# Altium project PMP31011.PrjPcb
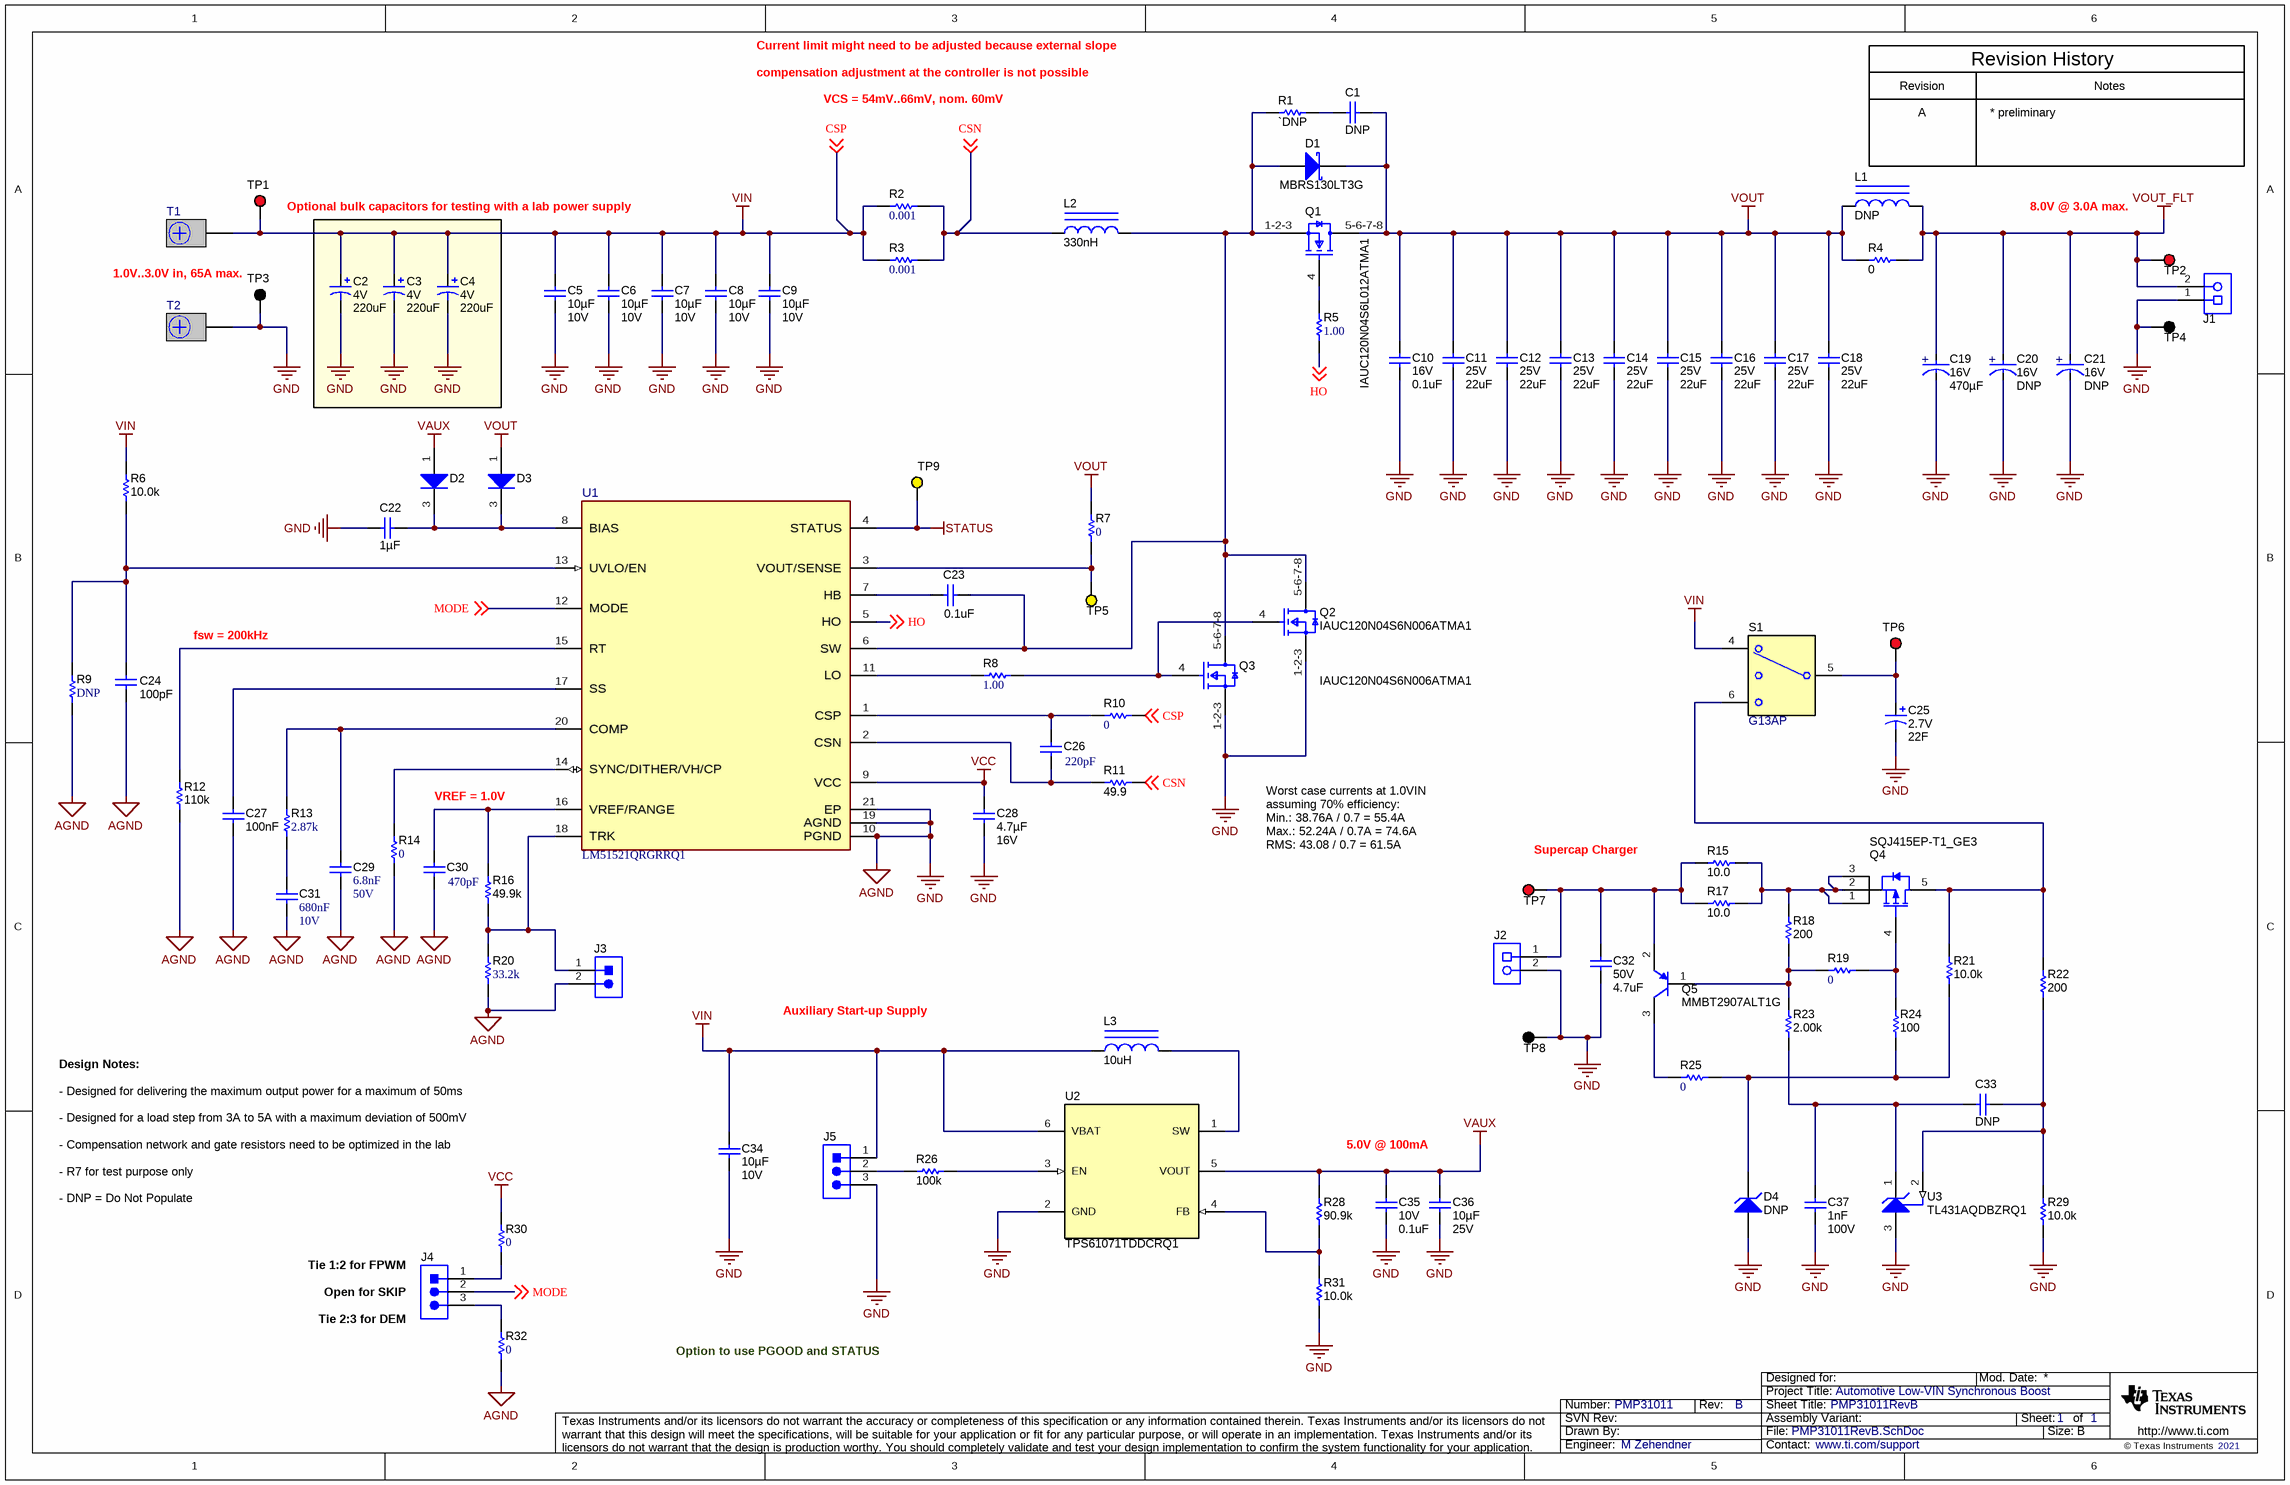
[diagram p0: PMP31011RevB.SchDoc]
TechSupport: www.ti.com/support; SCH_Rev: B; PRJ_Title: Automotive Low-VIN Synchronous Boost; PRJ_Number: PMP31011; PRJ_Engineer: M Zehendner; CopyrightYear: 2021
1 sheet, 100 parts. Net scope: global (net labels, ports and power ports of the same name join across sheets).
Board file: PMP31011_PCB.PcbDoc

## Sheet PMP31011RevB.SchDoc: PMP31011RevB
size 431 x 279 mm; DocumentNumber: 1; Revision: A; SheetNumber: 1; SheetTotal: 1; PageSetup: Record=PageOptions¦CenterHorizontal=True¦CenterVertical=True¦PrintScale=0.62¦XCorrection=1.00¦YCorrection=1.00¦PrintKind=0¦BorderSize=5000000¦LeftOffset=0¦BottomOffset=0¦Orientation=2¦PaperLength=1000¦PaperWidth=1000¦Scale=100¦PaperSource=15¦PrintQuality=600¦MediaType=1¦DitherType=10¦PaperKind=Letter (8.5 x 11")¦PrintScaleMode=1

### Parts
C1  Cap_F: DNP  [0805_HV]  (hidden comment: GRM21BR72A153MA01L)
C2  VDC_V: 4V  ValueDisplayed: 220uF  [7343-20]  (hidden comment: EEFSX0G221ER)
C3  VDC_V: 4V  ValueDisplayed: 220uF  [7343-20]  (hidden comment: EEFSX0G221ER)
C4  VDC_V: 4V  ValueDisplayed: 220uF  [7343-20]  (hidden comment: EEFSX0G221ER)
C5  Cap_F: 10µF  VDC_V: 10V  [0603]  (hidden comment: GRM188Z71A106MA73D)
C6  Cap_F: 10µF  VDC_V: 10V  [0603]  (hidden comment: GRM188Z71A106MA73D)
C7  Cap_F: 10µF  VDC_V: 10V  [0603]  (hidden comment: GRM188Z71A106MA73D)
C8  Cap_F: 10µF  VDC_V: 10V  [0603]  (hidden comment: GRM188Z71A106MA73D)
C9  Cap_F: 10µF  VDC_V: 10V  [0603]  (hidden comment: GRM188Z71A106MA73D)
C10  VDC_V: 16V  ValueDisplayed: 0.1uF  [0402]  (hidden comment: GRM155R71C104JA88D)
C11  VDC_V: 25V  ValueDisplayed: 22uF  [1210_270]  (hidden comment: GRM32ER71E226KE15L)
C12  VDC_V: 25V  ValueDisplayed: 22uF  [1210_270]  (hidden comment: GRM32ER71E226KE15L)
C13  VDC_V: 25V  ValueDisplayed: 22uF  [1210_270]  (hidden comment: GRM32ER71E226KE15L)
C14  VDC_V: 25V  ValueDisplayed: 22uF  [1210_270]  (hidden comment: GRM32ER71E226KE15L)
C15  VDC_V: 25V  ValueDisplayed: 22uF  [1210_270]  (hidden comment: GRM32ER71E226KE15L)
C16  VDC_V: 25V  ValueDisplayed: 22uF  [1210_270]  (hidden comment: GRM32ER71E226KE15L)
C17  VDC_V: 25V  ValueDisplayed: 22uF  [1210_270]  (hidden comment: GRM32ER71E226KE15L)
C18  VDC_V: 25V  ValueDisplayed: 22uF  [1210_270]  (hidden comment: GRM32ER71E226KE15L)
C19  VDC_V: 16V  Cap_F: 470µF  [FP-HHXB160ARA471MJA0G_RADIAL-MFG]  (hidden comment: HHXB160ARA471MJA0G)
C20  VDC_V: 16V  Cap_F: DNP  [FP-HHXB160ARA471MJA0G_RADIAL-MFG]  (hidden comment: HHXB160ARA471MJA0G)
C21  VDC_V: 16V  Cap_F: DNP  [FP-HHXB160ARA471MJA0G_RADIAL-MFG]  (hidden comment: HHXB160ARA471MJA0G)
C22  Cap_F: 1µF  [0603]  (hidden comment: GRM188R71E105KA12D)
C23  ValueDisplayed: 0.1uF  [0402]  (hidden comment: GRM155R71H104ME14D)
C24  ValueDisplayed: 100pF  [0402]  (hidden comment: GRM1555C1H101JA01D)
C25  VDC_V: 2.7V  ValueDisplayed: 22F  [JUM_1600x3150]  (hidden comment: JUMT1226MHD)
C26  ValueDisplayed: 220pF  [0402]  (hidden comment: GRM155R71H221KA01D)
C27  Cap_F: 100nF  [0603]  (hidden comment: GRM188R71C104KA01D)
C28  Cap_F: 4.7µF  VDC_V: 16V  [0603]  (hidden comment: GRM188Z71C475KE21D)
C29  Cap_F: 6.8nF  VDC_V: 50V  [0603]  (hidden comment: GRM188R71H682KA01D)
C30  ValueDisplayed: 470pF  [0402]  (hidden comment: GRM1555C1H471JA01D)
C31  Cap_F: 680nF  VDC_V: 10V  [0603]  (hidden comment: GRM188R71A684KA61D)
C32  VDC_V: 50V  ValueDisplayed: 4.7uF  [1210_270]  (hidden comment: GRM32ER71H475KA88L)
C33  Cap_F: DNP  [0603]  (hidden comment: GRM188R72A102KA01D)
C34  Cap_F: 10µF  VDC_V: 10V  [0603]  (hidden comment: GRM188Z71A106MA73D)
C35  VDC_V: 10V  ValueDisplayed: 0.1uF  [0402]  (hidden comment: GRM155R71A104KA01D)
C36  Cap_F: 10µF  VDC_V: 25V  [0805_HV]  (hidden comment: GRM21BZ71E106KE15L)
C37  Cap_F: 1nF  VDC_V: 100V  [0603]  (hidden comment: GRM188R72A102KA01D)
D1  MBRS130LT3G  [SMB]
D2  BAS16LT1G  [SOT-23]  (value not drawn)
D3  BAS16LT1G  [SOT-23]  (value not drawn)
D4  DNP  [SOD-523]
J1  691 101 710 002  [Wurth_691101710002]  (value not drawn)
J2  691 101 710 002  [Wurth_691101710002]  (value not drawn)
J3  61300211121  [WURTH_61300211121]  (value not drawn)
J4  61300311121  [WURTH_61300311121]  (value not drawn)
J5  61300311121  [WURTH_61300311121]  (value not drawn)
L1  ValueDisplayed: DNP  [XEL4014]  (hidden comment: XEL4014-221MEB)
L2  Ind_H: 330nH  [FP-ETQP8MR33JFA_SMT_INDUCTOR_12MM6_13MM2-MFG]  (hidden comment: ETQP8MR33JFA)
L3  ValueDisplayed: 10uH  [LPS4018]  (hidden comment: LPS4018-103MRB)
Q1  IAUC120N04S6L012ATMA1  [FP-IAUC120N04S6N009ATMA1_TDSON8-MFG]
Q2  IAUC120N04S6N006ATMA1  [FP-IAUC120N04S6N009ATMA1_TDSON8-MFG]
Q3  IAUC120N04S6N006ATMA1  [FP-IAUC120N04S6N009ATMA1_TDSON8-MFG]
Q4  SQJ415EP-T1_GE3  [PowerPAK_SO-8L]
Q5  MMBT2907ALT1G  [SOT-23]
R1  ValueDisplayed: `DNP  [1206]  (hidden comment: CSR1206FTR820)
R2  ValueDisplayed: 0.001  [2512]  (hidden comment: ERJ-M1WTF1M0U)
R3  ValueDisplayed: 0.001  [2512]  (hidden comment: ERJ-M1WTF1M0U)
R4  ValueDisplayed: 0  [2512_WIDE_VISHAY]  (hidden comment: RCL12250000Z0EG)
R5  ValueDisplayed: 1.00  [0603]  (hidden comment: CRCW06031R00FKEA)
R6  ValueDisplayed: 10.0k  [0603]  (hidden comment: CRCW060310K0FKEA)
R7  ValueDisplayed: 0  [0603]  (hidden comment: CRCW06030000Z0EA)
R8  ValueDisplayed: 1.00  [0603]  (hidden comment: CRCW06031R00FKEA)
R9  ValueDisplayed: DNP  [0603]  (hidden comment: CRCW06030000Z0EA)
R10  ValueDisplayed: 0  [0402]  (hidden comment: CRCW04020000Z0ED)
R11  ValueDisplayed: 49.9  [0402]  (hidden comment: CRCW040249R9FKED)
R12  ValueDisplayed: 110k  [0603]  (hidden comment: CRCW0603110KFKEA)
R13  ValueDisplayed: 2.87k  [0603]  (hidden comment: CRCW06032K87FKEA)
R14  ValueDisplayed: 0  [0402]  (hidden comment: CRCW04020000Z0ED)
R15  ValueDisplayed: 10.0  [1206]  (hidden comment: CRCW120610R0FKEA)
R16  ValueDisplayed: 49.9k  [0603]  (hidden comment: CRCW060349K9FKEA)
R17  ValueDisplayed: 10.0  [1206]  (hidden comment: CRCW120610R0FKEA)
R18  ValueDisplayed: 200  [0603]  (hidden comment: CRCW0603200RFKEA)
R19  ValueDisplayed: 0  [0603]  (hidden comment: CRCW06030000Z0EA)
R20  ValueDisplayed: 33.2k  [0603]  (hidden comment: CRCW060333K2FKEA)
R21  ValueDisplayed: 10.0k  [0603]  (hidden comment: CRCW060310K0FKEA)
R22  ValueDisplayed: 200  [0603]  (hidden comment: CRCW0603200RFKEA)
R23  ValueDisplayed: 2.00k  [0603]  (hidden comment: CRCW06032K00FKEA)
R24  ValueDisplayed: 100  [0603]  (hidden comment: CRCW0603100RFKEA)
R25  ValueDisplayed: 0  [0603]  (hidden comment: CRCW06030000Z0EA)
R26  ValueDisplayed: 100k  [0603]  (hidden comment: CRCW0603100KJNEA)
R28  ValueDisplayed: 90.9k  [0402]  (hidden comment: CRCW040290K9FKED)
R29  ValueDisplayed: 10.0k  [0603]  (hidden comment: CRCW060310K0FKEA)
R30  ValueDisplayed: 0  [0603]  (hidden comment: CRCW06030000Z0EA)
R31  ValueDisplayed: 10.0k  [0402]  (hidden comment: CRCW040210K0FKED)
R32  ValueDisplayed: 0  [0603]  (hidden comment: CRCW06030000Z0EA)
S1  G13AP  [SW_G1xAP]
T1  CB35-36-CY  [CB35-36-CY]  (value not drawn)
T2  CB35-36-CY  [CB35-36-CY]  (value not drawn)
TP1  5010  [Keystone5010]  (value not drawn)
TP2  5010  [Keystone5010]  (value not drawn)
TP3  5011  [Keystone5011]  (value not drawn)
TP4  5011  [Keystone5011]  (value not drawn)
TP5  5014  [Keystone5014]  (value not drawn)
TP6  5010  [Keystone5010]  (value not drawn)
TP7  5010  [Keystone5010]  (value not drawn)
TP8  5011  [Keystone5011]  (value not drawn)
TP9  5014  [Keystone5014]  (value not drawn)
U1  LM51521QRGRRQ1  [RGR0020C-MFG]
U2  TPS61071TDDCRQ1  [DDC0006A_N]
U3  TL431AQDBZRQ1  [DBZ0003A_N]

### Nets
AGND: C2.2(-) C3.2(-) C4.2(-) C5.2 C6.2 C7.2 C8.2 C9.2 C10.2 C11.2 C12.2 C13.2 C14.2 C15.2 C16.2 C17.2 C18.2 C19.1(CATHODE) C20.1(CATHODE) C21.1(CATHODE) C22.2 C24.2 C25.2(-) C27.2 C28.2 C29.2 C30.2 C31.2 C32.2 C34.2 C35.2 C36.2 C37.2 D4.2(A) J1.1 J2.2 J3.2 J5.3 Q2.1-2-3(S) Q3.1-2-3(S) R9.1 R12.1 R14.1 R20.1 R29.1 R31.1 R32.1 T2.1 TP3.1 TP4.1 TP8.1 U1.10(PGND) U1.19(AGND) U1.21(EP) U2.2(GND) U3.3(ANODE)  [also labelled GND]
STATUS: TP9.1 U1.4(STATUS)
VAUX: C35.1 C36.1 D2.1(A) R28.2 U2.5(VOUT)
VCC: C28.1 R30.2 U1.9(VCC)
VIN: C2.1(+) C3.1(+) C4.1(+) C5.1 C6.1 C7.1 C8.1 C9.1 C34.1 J5.1 L3.1 R2.2 R3.2 R6.2 R10.2 S1.4 T1.1 TP1.1 U2.6(VBAT) ; off-sheet CSP  [also labelled CSP]
VOUT: C1.1 C10.1 C11.1 C12.1 C13.1 C14.1 C15.1 C16.1 C17.1 C18.1 D1.1(K) D3.1(A) L1.1 Q1.5-6-7-8(D) R4.1 R7.2
VOUT_FLT: C19.2(ANODE) C20.2(ANODE) C21.2(ANODE) J1.2 L1.2 R4.2 TP2.1
CSN: L2.1 R2.1 R3.1 R11.2 ; off-sheet CSN
HO: R5.1 U1.5(HO) ; off-sheet HO
MODE: J4.2 U1.12(MODE) ; off-sheet MODE
NetC1_2: C1.2 R1.2
NetC22_1: C22.1 D2.3(K) D3.3(K) U1.8(BIAS)
NetC23_1: C23.1 U1.7(HB)
NetC23_2: C23.2 D1.2(A) L2.2 Q1.1-2-3(S) Q2.5-6-7-8(D) Q3.5-6-7-8(D) R1.1 U1.6(SW)
NetC24_1: C24.1 R6.1 R9.2 U1.13(UVLO/EN)
NetC25_1: C25.1(+) S1.5(COM) TP6.1
NetC26_1: C26.1 R10.1 U1.1(CSP)
NetC26_2: C26.2 R11.1 U1.2(CSN)
NetC27_1: C27.1 U1.17(SS)
NetC29_1: C29.1 R13.2 U1.20(COMP)
NetC30_1: C30.1 R16.2 U1.16(VREF/RANGE)
NetC31_1: C31.1 R13.1
NetC32_1: C32.1 J2.1 Q5.2(E) R15.1 R17.1 TP7.1
NetC33_1: C33.1 C37.1 R23.1 U3.1(CATHODE)
NetC33_2: C33.2 R22.1 R29.2 U3.2(REF)
NetD4_1: D4.1(K) R21.1 R24.1 R25.2
NetJ3_1: J3.1 R16.1 R20.2 U1.18(TRK)
NetJ4_1: J4.1 R30.1
NetJ4_3: J4.3 R32.2
NetJ5_2: J5.2 R26.2
NetL3_2: L3.2 U2.1(SW)
NetQ1_4: Q1.4(G) R5.2
NetQ2_4: Q2.4(G) Q3.4(G) R8.1
NetQ4_1: Q4.1(S) Q4.2(S) Q4.3(S) R15.2 R17.2 R18.2
NetQ4_4: Q4.4(G) R19.2 R24.2
NetQ4_5: Q4.5(D) R21.2 R22.2 S1.6
NetQ5_1: Q5.1(B) R18.1 R19.1 R23.2
NetQ5_3: Q5.3(C) R25.1
NetR7_1: R7.1 TP5.1 U1.3(VOUT/SENSE)
NetR8_2: R8.2 U1.11(LO)
NetR12_2: R12.2 U1.15(RT)
NetR14_2: R14.2 U1.14(SYNC/DITHER/VH/CP)
NetR26_1: R26.1 U2.3(EN)
NetR28_1: R28.1 R31.2 U2.4(FB)

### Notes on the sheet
- Current limit might need to be adjusted because external slope
- compensation adjustment at the controller is not possible
- VCS = 54mV..66mV, nom. 60mV
- Revision
- Revision History
- Notes
- A
- * preliminary
- (near TP1) Optional bulk capacitors for testing with a lab power supply
- 8.0V @ 3.0A max.
- 1.0V..3.0V in, 65A max.
- fsw = 200kHz
- VREF = 1.0V
- Worst case currents at 1.0VIN assuming 70% efficiency:
  Min.: 38.76A / 0.7 = 55.4A
  Max.: 52.24A / 0.7A = 74.6A
  RMS: 43.08 / 0.7 = 61.5A
- (near TP7) Supercap Charger
- Auxiliary Start-up Supply
- Design Notes:
- - Designed for delivering the maximum output power for a maximum of 50ms
- - Designed for a load step from 3A to 5A with a maximum deviation of 500mV
- - R7 for test purpose only
- - Compensation network and gate resistors need to be optimized in the lab
- 5.0V @ 100mA
- - DNP = Do Not Populate
- (near J4) Tie 1:2 for FPWM
- (near J4) Open for SKIP
- (near J4) Tie 2:3 for DEM
- Option to use PGOOD and STATUS

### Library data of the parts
C1 = CMP-0008366-2: CAP, CERM, 0.015 uF, 100 V, +/- 20%, X7R, 0805; Manufacturer: MuRata; TaMin_C: -55°C; Polarized: N; SizeAreaWB_mm2: 6.75; Value1: Unknown; U/M: EA; TaMax_C: 125°C; SizeZ_mm: 1.45; SizeX_mm: 2; SizeY_mm: 1.25; Cap_Case: 0805; Value2: 100V; SizeArea_mm2: 2.5; AEC Category: Q200
C2-C4 = CMP-0012259-4: CAP, Aluminum Polymer, 220 uF, 4 V, +/- 20%, 9 ohm, 7343-20, SMD; Manufacturer: Panasonic; TaMin_C: -40°C; ESR_ohm: 9; Polarized: Y; Value1: 9 ohm; Value: 220uF; TaMax_C: 105°C; CompType: Capacitor; AEC Qualified: N; Cap_F: 220µF; IRMS_A: 3A; AEC Category: Q200; SizeAreaWB_mm2: 58.59; SizeArea_mm2: 31.39; SizeX_mm: 7.3; SizeY_mm: 4.3; SizeZ_mm: 2.0
C5-C9 C34 = CMP-0007497-5: CAP, CERM, 10 uF, 10 V, +/- 20%, X7R, 0603; Manufacturer: MuRata; TaMin_C: -55°C; Polarized: N; SizeAreaWB_mm2: 4.68; Value1: Unknown; U/M: EA; Value: 10uF; TaMax_C: 125°C; SizeZ_mm: 1; SizeX_mm: 1.6; SizeY_mm: 0.8; SizeArea_mm2: 1.28; AEC Category: Q200
C10 = CMP-0006640-2: CAP, CERM, 0.1 uF, 16 V, +/- 5%, X7R, 0402; Manufacturer: MuRata; TaMin_C: -55°C; Polarized: N; SizeAreaWB_mm2: 3; Value1: Unknown; U/M: EA; Value: 0.1uF; TaMax_C: 125°C; SizeZ_mm: 0.6; SizeX_mm: 1; SizeY_mm: 0.5; Cap_F: 100nF; AEC Category: Q200
C11-C18 = CMP-0009224-2: CAP, CERM, 22 uF, 25 V, +/- 10%, X7R, 1210; Manufacturer: MuRata; TaMin_C: -55°C; Polarized: N; SizeAreaWB_mm2: 14.7; Value1: Unknown; U/M: EA; Value: 22uF; TaMax_C: 125°C; SizeZ_mm: 2.7; SizeX_mm: 3.2; SizeY_mm: 2.5; Cap_Case: 1210; SizeArea_mm2: 8; Cap_F: 22µF; AEC Category: Q200
C19-C21 = CMP-0086437-1: Cap Aluminum Polymer 470uF 16VDC 20% (10 X 10mm) SMD 0.018 Ohm 2600mA 5000h 105C Automotive T/R; Manufacturer: United Chemi-Con; AEC Qualified: Yes; SizeZ_mm: 10.3mm; IRMS_A: 2.6A; Symbol Name: SYM-HHXB160ARA471MJA0G; AEC Grade: Grade 2
C22 = CMP-0007405-4: CAP, CERM, 1 uF, 25 V, +/- 10%, X7R, 0603; Manufacturer: MuRata; TaMin_C: -55°C; Polarized: N; SizeAreaWB_mm2: 4.68; Value1: Unknown; U/M: EA; Value: 1uF; TaMax_C: 125°C; SizeZ_mm: 1; SizeX_mm: 1.6; SizeY_mm: 0.8; Value2: 25V; SizeArea_mm2: 1.28; AEC Category: Q200
C23 = CMP-0006675-2: CAP, CERM, 0.1 uF, 50 V, +/- 20%, X7R, 0402; Manufacturer: MuRata; TaMin_C: -55°C; Polarized: N; SizeAreaWB_mm2: 3; Value1: Unknown; U/M: EA; Value: 0.1uF; TaMax_C: 125°C; SizeZ_mm: 0.6; SizeX_mm: 1; SizeY_mm: 0.5; Value2: 50V; Cap_F: 100nF; AEC Category: Q200
C24 = CMP-0006410-2: CAP, CERM, 100 pF, 50 V, +/- 5%, C0G/NP0, 0402; Manufacturer: MuRata; TaMin_C: -55°C; Polarized: N; SizeAreaWB_mm2: 3; Value1: Unknown; U/M: EA; Value: 100pF; TaMax_C: 125°C; SizeZ_mm: 0.6; SizeX_mm: 1; SizeY_mm: 0.5; Value2: 50V; AEC Category: Q200
C25 = CMP-0084050-1: CAP, Electric Double Layer, 22000000 µF, 2.7 V,+/- 20%, 0.07 ohm, TH; Manufacturer: Nichicon; TaMin_C: -25°C; ESR_ohm: 0.07; Polarized: Y; SizeAreaWB_mm2: 324; Value: 22000000uF; TaMax_C: 70°C; SizeZ_mm: 33.5; SizeX_mm: 16; Cap_Case: 16x31.5mm; SizeArea_mm2: 256; CompType: Capacitor; AEC Qualified: N; AEC Category: Q200
C26 = CMP-0006682-2: CAP, CERM, 220 pF, 50 V, +/- 10%, X7R, 0402; Manufacturer: MuRata; TaMin_C: -55°C; Polarized: N; SizeAreaWB_mm2: 3; Value1: Unknown; U/M: EA; Value: 220pF; TaMax_C: 125°C; SizeZ_mm: 0.6; SizeX_mm: 1; SizeY_mm: 0.5; Value2: 50V; AEC Category: Q200
C27 = CMP-0007378-5: CAP, CERM, 0.1 uF, 16 V, +/- 10%, X7R, 0603; Manufacturer: MuRata; TaMin_C: -55°C; Polarized: N; SizeAreaWB_mm2: 4.68; Value1: Unknown; U/M: EA; Value: 0.1uF; TaMax_C: 125°C; SizeZ_mm: 1; SizeX_mm: 1.6; SizeY_mm: 0.8; Value2: 16V; SizeArea_mm2: 1.28; AEC Category: Q200
C28 = CMP-0064936-4: CAP, CERM, 4.7 uF, 16 V,+/- 10%, X7R, 0603; Manufacturer: MuRata; TaMin_C: -55°C; Polarized: N; SizeAreaWB_mm2: 4.68; Value1: Unknown; U/M: EA; Value: 4.7uF; TaMax_C: 125°C; SizeZ_mm: 1; SizeX_mm: 1.6; SizeY_mm: 0.8; SizeArea_mm2: 1.28; AEC Category: Q200
C29 = CMP-0007462-4: CAP, CERM, 6800 pF, 50 V, +/- 10%, X7R, 0603; Manufacturer: MuRata; TaMin_C: -55°C; Polarized: N; SizeAreaWB_mm2: 4.68; Value1: Unknown; U/M: EA; Value: 6800pF; TaMax_C: 125°C; SizeZ_mm: 1; SizeX_mm: 1.6; SizeY_mm: 0.8; SizeArea_mm2: 1.28; AEC Category: Q200
C30 = CMP-0006470-2: CAP, CERM, 470 pF, 50 V, +/- 5%, C0G/NP0, 0402; Manufacturer: MuRata; TaMin_C: -55°C; Polarized: N; SizeAreaWB_mm2: 3; Value1: Unknown; U/M: EA; Value: 470pF; TaMax_C: 125°C; SizeZ_mm: 0.6; SizeX_mm: 1; SizeY_mm: 0.5; Value2: 50V; AEC Category: Q200
C31 = CMP-0007375-4: CAP, CERM, 0.68 uF, 10 V, +/- 10%, X7R, 0603; Manufacturer: MuRata; TaMin_C: -55°C; Polarized: N; SizeAreaWB_mm2: 4.68; Value1: Unknown; U/M: EA; Value: 0.68uF; TaMax_C: 125°C; SizeZ_mm: 1; SizeX_mm: 1.6; SizeY_mm: 0.8; SizeArea_mm2: 1.28; AEC Category: Q200
C32 = CMP-0009228-2: CAP, CERM, 4.7 uF, 50 V, +/- 10%, X7R, 1210; Manufacturer: MuRata; TaMin_C: -55°C; ESR_ohm: 2m; Polarized: N; SizeAreaWB_mm2: 14.7; Value1: 0.002 ohm; U/M: EA; Value: 4.7uF; TaMax_C: 125°C; SizeZ_mm: 2.7; SizeX_mm: 3.2; SizeY_mm: 2.5; Cap_Case: 1210; SizeArea_mm2: 8; Cap_F: 4.7µF; AEC Category: Q200
C33 = CMP-0007467-4: CAP, CERM, 1000 pF, 100 V, +/- 10%, X7R, 0603; Manufacturer: MuRata; TaMin_C: -55°C; Polarized: N; SizeAreaWB_mm2: 4.68; Value1: Unknown; U/M: EA; Value: 1000pF; TaMax_C: 125°C; SizeZ_mm: 1; SizeX_mm: 1.6; SizeY_mm: 0.8; Value2: 100V; SizeArea_mm2: 1.28; AEC Category: Q200
C35 = CMP-0006629-2: CAP, CERM, 0.1 uF, 10 V, +/- 10%, X7R, 0402; Manufacturer: MuRata; TaMin_C: -55°C; Polarized: N; SizeAreaWB_mm2: 3; Value1: Unknown; U/M: EA; Value: 0.1uF; TaMax_C: 125°C; SizeZ_mm: 0.6; SizeX_mm: 1; SizeY_mm: 0.5; Cap_F: 100nF; AEC Category: Q200
C36 = CMP-0008378-2: CAP, CERM, 10 uF, 25 V, +/- 10%, X7R, 0805; Manufacturer: MuRata; TaMin_C: -55°C; Polarized: N; SizeAreaWB_mm2: 6.75; Value1: Unknown; U/M: EA; Value: 10uF; TaMax_C: 125°C; SizeZ_mm: 1.45; SizeX_mm: 2; SizeY_mm: 1.25; Cap_Case: 0805; SizeArea_mm2: 2.5; AEC Category: Q200
C37 = CMP-0007467-4: CAP, CERM, 1000 pF, 100 V, +/- 10%, X7R, 0603; Manufacturer: MuRata; TaMin_C: -55°C; Polarized: N; SizeAreaWB_mm2: 4.68; Value1: Unknown; U/M: EA; Value: 1000pF; TaMax_C: 125°C; SizeZ_mm: 1; SizeX_mm: 1.6; SizeY_mm: 0.8; SizeArea_mm2: 1.28; AEC Category: Q200
D1 = CMP-0028527-2: Diode, Schottky, 30 V, 1 A, SMB; Manufacturer: ON Semiconductor; SizeZ_mm: 2.6; TJmax_C: 125°C; Green_Lifecycle: Not Set; RJC_CperW: 12; SizeY_mm: 3.81; Vr_V: 30V; Value: 30V; Value1: 1A; SizeArea_mm2: 21.336; AEC Category: Q101; Vf_V: 395mV; SizeAreaWB_mm2: 44.156; Value2: 0.395V; SizeX_mm: 5.6; Green_REACh: Incomplete
D2 D3 = CMP-0029193-2: Diode, Switching, 100 V, 0.2 A, SOT-23; Manufacturer: ON Semiconductor; Value: 100V; Green_Lifecycle: Active; SizeAreaWB_mm2: 14; Vf_V: 1.25V; SizeZ_mm: 1.1; AEC Qualified: N; SizeX_mm: 2.5; Green_REACh: Passed; AEC Category: Q101; Value1: 0.2A; SizeY_mm: 3; SizeArea_mm2: 7.5; Io_A: 200mA; TJmax_C: 150°C
D4 = CMP-0005892-4: Diode, Zener, 2.7 V, 300 mW, SOD-523; Manufacturer: Diodes Inc.; PartNumber: BZT52C2V7T-7; Value: 2.7V; SizeY_mm: 0.9; AEC Category: Q101; SizeX_mm: 1.7; Power_W: 300mW; Value1: 0.3W; SizeZ_mm: 0.65; SizeAreaWB_mm2: 5.13; RJA_CperW: 417; SizeArea_mm2: 1.53
J1 J2 = CMP-0054828-1: Terminal Block, 5 mm, 2x1, Tin, TH; Manufacturer: Wurth Elektronik; CNHeader: FALSE; Green_Lifecycle: Active; Green_REACh: Passed; CT: TRUE
J3 = CMP-0054794-2: Header, 2.54 mm, 2x1, Gold, TH; Manufacturer: Wurth Elektronik; Shrouded: N; Gender: Male; Green_REACh: Passed; Pitch_mm: 2.54; Green_Lifecycle: Active; Row_Count: 1; Cert_UL: Y
J4 J5 = CMP-0054796-2: Header, 2.54 mm, 3x1, Gold, TH; Manufacturer: Wurth Elektronik; Pitch_mm: 2.54; Green_Lifecycle: Active; Cert_UL: Y; Shrouded: N; Green_REACh: Passed; Gender: Male; Row_Count: 1
L1 = CMP-0061070-1: Inductor, Shielded, Composite, 220 nH, 12 A, 0.0075 ohm, AEC-Q200 Grade 1, SMD; Manufacturer: Coilcraft; Isat: 18.2A @ 30% inductance drop; Irms: 12A @ 40C rise; SizeAreaWB_mm2: 25; DCR_ohm: 7.5m; Value: 220nH; Imax_A: 12A; SizeZ_mm: 1.4; SizeX_mm: 4; SizeArea_mm2: 16; AEC Qualified: Y; AEC Grade: 1; AEC Category: Q200
L2 = CMP-0091958-2: Power Inductor, Aec-Q200, Shld, 330Nh; Inductance: 330Nh; Rms Current (Irms): 44.4A; Inductor Construction: shielded;...; Manufacturer: Panasonic; Standoff Height: 0.05mm; SizeZ_mm: 8.05mm; Test Frequency: 100kHz; Shrouded: true; DCR_ohm: 770µ; Isat: 84.5A; AEC Qualified: Yes; AEC Grade: Grade 0; Tolerance_%: 20%; Imax_A: 53.5A; Material: Metal Composite
L3 = CMP-0060471-1: Inductor, Shielded Drum Core, Ferrite, 10 uH, 1.25 A, 0.18 ohm, SMD; Manufacturer: Coilcraft; Isat: 1.3A @ 30% inductance drop; Irms: 1.25A @ 40C rise; Green_Lifecycle: Not Set; SizeAreaWB_mm2: 24.01; DCR_ohm: 0.18; Green_REACh: Incomplete; Value: 10uH; Imax_A: 1.25A; SizeZ_mm: 1.7; SizeX_mm: 3.9; SizeArea_mm2: 15.21; Ind_H: 10µH; AEC Qualified: N; AEC Category: Q200
Q1-Q3 = CMP-0086959-1: Trans Mosfet N-ch 40V 120A 8-PIN Pg-tdson T/R; Manufacturer: Infineon; PartNumber: IAUC120N04S6N010ATMA1; SizeZ_mm: 1.1mm; Symbol Name: SYM-IAUC120N04S6N010ATMA1; Rdson45_ohm: 930µ; QgTyp_nC: 81nC @ 10V; Vgs_V: 20V; AEC Qualified: Yes; ChMode: False
Q4 = CMP-0083987-2: MOSFET, P-CH, -40 V, -30 A, AEC-Q101, PowerPAK_SO-8L; Alternate Manufacturer: None; Manufacturer: Vishay-Semiconductor; Rdson45_ohm: 0.024; QgTyp_nC: 73; Value: -60V; ChMode: Enhancement; SizeAreaWB_mm2: 58.1095; Value1: 0.024 ohm; SizeZ_mm: 1.14; SizeArea_mm2: 31.5495; ChType: P; SizeY_mm: 5.13; AEC Qualified: Y; AEC Category: Q101; IdsMax_A: -52A; SizeX_mm: 6.15; Vgs_V: 20V; Value2: 73 nC
Q5 = CMP-0000344-2: Transistor, PNP, 60 V, 0.6 A, SOT-23; Manufacturer: ON Semiconductor; TaMax_C: 150°C; Value1: 0.6 A; Vcesat1_V: 1.6V; SizeX_mm: 2.5; SizeY_mm: 3; TaMin_C: -55°C; IcRated_A: 600mA; CompType: BJT; SizeZ_mm: 1.1; Value: 60 V; SizeArea_mm2: 7.5; NPN: 0; Vceo_V: 60V; PNP: 1; AEC Category: Q101; SizeAreaWB_mm2: 14; U/M: EA
R1 = CMP-0017275-2: RES, 0.82, 1%, 0.5 W, 1206; Manufacturer: Stackpole Electronics Inc; Power_W: 500mW; TempCo: 100 ppm/C; Value_Code: R820; U/M: EA; Value: 0.82; EIA_Code: E96; SizeX_mm: 3.2; SizeY_mm: 1.6; SizeZ_mm: 1.35; Value2: 0.5W; SizeArea_mm2: 5.12; AEC Category: Q200
R2 R3 = CMP-0015817-2: RES, 0.001, 1%, 1 W, 2512; Manufacturer: Panasonic; Power_W: 1W; TempCo: ppm/C; Value_Code: 1L000; U/M: EA; Value: 0.001; EIA_Code: E96; Res_ohm: 1m; SizeX_mm: 6.3; SizeY_mm: 3.2; SizeZ_mm: 0.71; SizeArea_mm2: 20.16; AEC Category: Q200
R4 = CMP-0015368-2: RES, 0, 5%, 2 W, 2512 WIDE; Manufacturer: Vishay Draloric; Power_W: 2W; TempCo: ppm/C; Value_Code: 0000; U/M: EA; Value: 0; EIA_Code: E24; AEC Category: Q200
R5 R8 = CMP-0022170-4: RES, 1.00, 1%, 0.1 W, AEC-Q200 Grade 0, 0603; Manufacturer: Vishay-Dale; Power_W: 100mW; TempCo: 100 ppm/C; Value_Code: 1R00; Value: 1.00; EIA_Code: E96; Res_ohm: 1; SizeX_mm: 1.6; SizeY_mm: 0.8; Value2: 0.1W; SizeArea_mm2: 1.28; AEC Qualified: Y; VDC_V: 75V; AEC Category: Q200; AEC Grade: 0
R6 R21 R29 = CMP-0021998-4: RES, 10.0 k, 1%, 0.1 W, AEC-Q200 Grade 0, 0603; Manufacturer: Vishay-Dale; Power_W: 100mW; TempCo: 100 ppm/C; Value_Code: 10k0; Value: 10.0k; EIA_Code: E96; Res_ohm: 10k; SizeX_mm: 1.6; SizeY_mm: 0.8; SizeZ_mm: 1; Value2: 0.1W; SizeArea_mm2: 1.28; AEC Qualified: Y; VDC_V: 75V; AEC Category: Q200; AEC Grade: 0
R7 R9 R19 R25 R30 R32 = CMP-0025697-4: RES, 0, 5%, 0.1 W, AEC-Q200 Grade 0, 0603; Manufacturer: Vishay-Dale; Power_W: 100mW; TempCo: 200 ppm/C; Value_Code: 0000; Value: 0; EIA_Code: E24; SizeX_mm: 1.6; SizeY_mm: 0.8; SizeZ_mm: 1; Value2: 0.1W; SizeArea_mm2: 1.28; AEC Qualified: Y; VDC_V: 75V; AEC Category: Q200
R10 R14 = CMP-0026822-3: RES, 0, 5%, 0.063 W, AEC-Q200 Grade 0, 0402; Manufacturer: Vishay-Dale; Power_W: 63mW; TempCo: 200 ppm/C; Value_Code: 0000; Value: 0; EIA_Code: E24; SizeX_mm: 1; SizeY_mm: 0.5; SizeZ_mm: 0.6; Value2: 0.063W; AEC Qualified: Y; VDC_V: 50V; AEC Category: Q200
R11 = CMP-0026404-2: RES, 49.9, 1%, 0.063 W, AEC-Q200 Grade 0, 0402; Manufacturer: Vishay-Dale; Power_W: 63mW; TempCo: 100 ppm/C; Value_Code: 49R9; Value: 49.9; EIA_Code: E96; SizeX_mm: 1; SizeY_mm: 0.5; SizeZ_mm: 0.6; Value2: 0.063W; AEC Qualified: Y; VDC_V: 50V; AEC Category: Q200; AEC Grade: 0
R12 = CMP-0022008-4: RES, 110 k, 1%, 0.1 W, AEC-Q200 Grade 0, 0603; Manufacturer: Vishay-Dale; Power_W: 100mW; TempCo: 100 ppm/C; Value: 110k; EIA_Code: E96; SizeX_mm: 1.6; SizeY_mm: 0.8; SizeZ_mm: 1; Value2: 0.1W; SizeArea_mm2: 1.28; AEC Qualified: Y; VDC_V: 75V; AEC Category: Q200; AEC Grade: 0
R13 = CMP-0022283-4: RES, 2.87 k, 1%, 0.1 W, AEC-Q200 Grade 0, 0603; Manufacturer: Vishay-Dale; Power_W: 100mW; TempCo: 100 ppm/C; Value_Code: 2k87; Value: 2.87k; EIA_Code: E96; SizeX_mm: 1.6; SizeY_mm: 0.8; SizeZ_mm: 1; Value2: 0.1W; SizeArea_mm2: 1.28; AEC Qualified: Y; VDC_V: 75V; AEC Category: Q200; AEC Grade: 0
R15 R17 = CMP-0016583-3: RES, 10.0, 1%, 0.25 W, AEC-Q200 Grade 0, 1206; Manufacturer: Vishay-Dale; Power_W: 250mW; TempCo: 100 ppm/C; Value_Code: 10R0; Value: 10.0; EIA_Code: E96; Res_ohm: 10; SizeX_mm: 3.2; SizeY_mm: 1.6; SizeZ_mm: 1.35; Value2: 0.25W; SizeArea_mm2: 5.12; AEC Qualified: Y; VDC_V: 200V; AEC Category: Q200; AEC Grade: 0
R16 = CMP-0022447-4: RES, 49.9 k, 1%, 0.1 W, AEC-Q200 Grade 0, 0603; Manufacturer: Vishay-Dale; Power_W: 100mW; TempCo: 100 ppm/C; Value_Code: 49k9; Value: 49.9k; EIA_Code: E96; SizeX_mm: 1.6; SizeY_mm: 0.8; SizeZ_mm: 1; Value2: 0.1W; SizeArea_mm2: 1.28; AEC Qualified: Y; VDC_V: 75V; AEC Category: Q200; AEC Grade: 0
R18 R22 = CMP-0022201-5: RES, 200, 1%, 0.1 W, AEC-Q200 Grade 0, 0603; Manufacturer: Vishay-Dale; Power_W: 100mW; TempCo: 100 ppm/C; Value_Code: 200R; Value: 200; EIA_Code: E96; SizeX_mm: 1.6; SizeY_mm: 0.8; SizeZ_mm: 1; Value2: 0.1W; SizeArea_mm2: 1.28; AEC Qualified: Y; VDC_V: 75V; AEC Category: Q200; AEC Grade: 0
R20 = CMP-0022339-4: RES, 33.2 k, 1%, 0.1 W, AEC-Q200 Grade 0, 0603; Manufacturer: Vishay-Dale; Power_W: 100mW; TempCo: 100 ppm/C; Value_Code: 33k2; Value: 33.2k; EIA_Code: E96; SizeX_mm: 1.6; SizeY_mm: 0.8; SizeZ_mm: 1; Value2: 0.1W; SizeArea_mm2: 1.28; AEC Qualified: Y; VDC_V: 75V; AEC Category: Q200; AEC Grade: 0
R23 = CMP-0022268-4: RES, 2.00 k, 1%, 0.1 W, AEC-Q200 Grade 0, 0603; Manufacturer: Vishay-Dale; Power_W: 100mW; TempCo: 100 ppm/C; Value_Code: 2k00; Value: 2.00k; EIA_Code: E96; Res_ohm: 2k; SizeX_mm: 1.6; SizeY_mm: 0.8; SizeZ_mm: 1; Value2: 0.1W; SizeArea_mm2: 1.28; AEC Qualified: Y; VDC_V: 75V; AEC Category: Q200; AEC Grade: 0
R24 = CMP-0021991-4: RES, 100, 1%, 0.1 W, AEC-Q200 Grade 0, 0603; Manufacturer: Vishay-Dale; Power_W: 100mW; TempCo: 100 ppm/C; Value_Code: 100R; Value: 100; EIA_Code: E96; SizeX_mm: 1.6; SizeY_mm: 0.8; SizeZ_mm: 1; Value2: 0.1W; SizeArea_mm2: 1.28; AEC Qualified: Y; VDC_V: 75V; AEC Category: Q200; AEC Grade: 0
R26 = CMP-0025698-4: RES, 100 k, 5%, 0.1 W, AEC-Q200 Grade 0, 0603; Manufacturer: Vishay-Dale; Power_W: 100mW; TempCo: 200 ppm/C; Value: 100k; EIA_Code: E24; SizeX_mm: 1.6; SizeY_mm: 0.8; SizeZ_mm: 1; Value2: 0.1W; SizeArea_mm2: 1.28; AEC Qualified: Y; VDC_V: 75V; AEC Category: Q200; AEC Grade: 0
R28 = CMP-0026605-2: RES, 90.9 k, 1%, 0.063 W, AEC-Q200 Grade 0, 0402; Manufacturer: Vishay-Dale; Power_W: 63mW; TempCo: 100 ppm/C; Value_Code: 90k9; Value: 90.9k; EIA_Code: E96; SizeX_mm: 1; SizeY_mm: 0.5; SizeZ_mm: 0.6; Value2: 0.063W; AEC Qualified: Y; VDC_V: 50V; AEC Category: Q200; AEC Grade: 0
R31 = CMP-0025958-3: RES, 10.0 k, 1%, 0.063 W, AEC-Q200 Grade 0, 0402; Manufacturer: Vishay-Dale; Power_W: 63mW; TempCo: 100 ppm/C; Value_Code: 10k0; Value: 10.0k; EIA_Code: E96; Res_ohm: 10k; SizeX_mm: 1; SizeY_mm: 0.5; SizeZ_mm: 0.6; Value2: 0.063W; AEC Qualified: Y; VDC_V: 50V; AEC Category: Q200; AEC Grade: 0
S1 = CMP-0002118-3: Switch, Toggle, SPDT 1Pos, TH; Manufacturer: NKK Switches; CurrentRating_mA: 400A; VDC_V: 28V; SwitchFunction: ON-OFF-ON; PositionCount: 1
T1 T2 = CMP-0055442-1: Terminal 50A Lug; Manufacturer: Panduit; CNHeader: FALSE; Green_Lifecycle: Not Set; Cert_CULUS: Y; Green_REACh: Incomplete; Voltage_V: 600V; CompType: Screw Terminal; ContactFinish: Copper
TP1 TP2 TP6 TP7 = CMP-0055147-1: Test Point, Multipurpose, Red, TH; Manufacturer: Keystone; CNHeader: FALSE; Green_Lifecycle: Active; Green_REACh: Passed; ContactFinish: Silver; CT: TRUE
TP3 TP4 TP8 = CMP-0055148-1: Test Point, Multipurpose, Black, TH; Manufacturer: Keystone; CNHeader: FALSE; Green_Lifecycle: Active; Green_REACh: Passed; ContactFinish: Silver; CT: TRUE
TP5 TP9 = CMP-0055151-1: Test Point, Multipurpose, Yellow, TH; Manufacturer: Keystone; CNHeader: FALSE; Green_Lifecycle: Active; Green_REACh: Passed; ContactFinish: Silver; CT: TRUE
U1 = CMP-0088589-2: Automotive Low-IQ Synchronous Boost Controller for Start-stop; Manufacturer: Texas Instruments; Max Duty Cycle: 96%; Min Supply Voltage: 3.8V; Max Supply Voltage: 42V; Standoff Height: 0mm; Output Voltage: 5-20V; Output Type: AdjustableProgrammable; TJmax_C: +150°C; SizeZ_mm: 1mm; TaMin_C: -40°C; Switching Frequency: 100-2200kHz; CompType: IC; Number Of Outputs: 1; Nominal Supply Current: 1.2mA; TaMax_C: +125°C; AEC Grade: Grade 1; AEC Qualified: Yes; AEC Category: Q200
U2 = CMP-0067186-2: Automotive Catalog Adjustable, 600-mA Switch, 90% Efficient PWM Boost Converter, DDC0006A (SOT-23-T-6); Manufacturer: Texas Instruments; SizeZ_mm: 0.87; SizeX_mm: 1.65; SizeY_mm: 2.95; SizeArea_mm2: 4.8675; CompType: IC; U/M: EA; SizeAreaWB_mm2: 10.4675
U3 = CMP-0033164-1: Automotive Catalog Adjustable Precision Shunt Regulator, 34 ppm / degC, 100 mA, -40 to 125 degC, 3-pin SOT-23 (DBZ), Green (RoHS & no Sb/Br); Manufacturer: Texas Instruments; SubFamily: Shunt Voltage Reference; Initial Accuracy @ 25/deg C(%): 1; Min Iz for Regulation(uA): 600; Iout/Iz(Max)(mA): 100; Temp Coeff(Typ)(ppm/ degree C): 34; VO Adj(Max)(V): 36; VO Adj(Min)(V): 2.495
